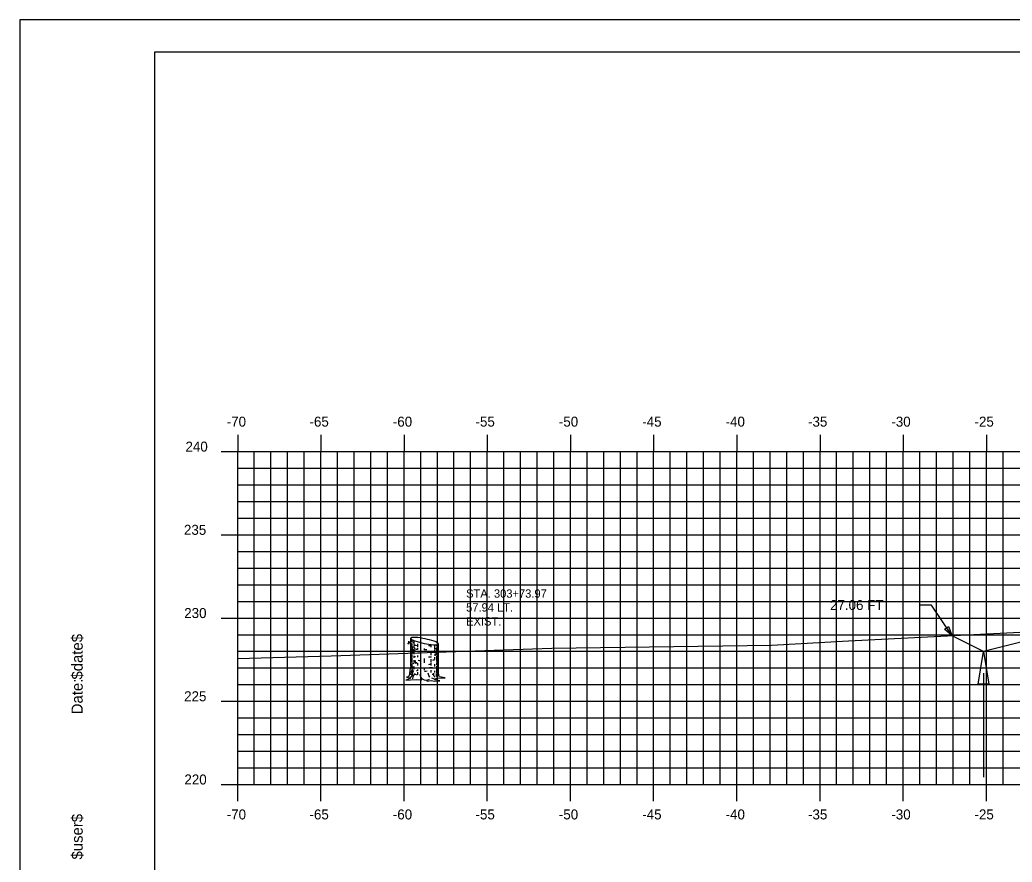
# Model space of a CAD drawing. Extents: x 1136767 to 1136937, y 608981 to 609091.
# Drawn here: x 1136767.3 to 1136826.9, y 609040.7 to 609091.3 of the extents above; entities that cross this region are included whole.
import ezdxf

# ---------------------------------------------------------------- set-up
doc = ezdxf.new("R2010")
doc.units = 0
for name, color, linetype in [('BORDER', 7, 'Continuous'), ('D_Drainage_Ditch_Line', 7, 'Continuous'), ('D_Roadway_SlopeLines', 7, 'Continuous'), ('D_Text_Monospaced', 7, 'Continuous'), ('D_Text_Standard', 7, 'Continuous'), ('H_V ANNOTATION', 7, 'Continuous'), ('MAJOR', 7, 'Continuous'), ('MINOR', 7, 'Continuous'), ('PLOT BOUNDARY', 7, 'Continuous'), ('S_Roadway_Centerline', 7, 'Continuous'), ('S_Trees_Conifer_Pay', 7, 'Continuous')]:
    doc.layers.add(name, color=color, linetype=linetype)

msp = doc.modelspace()

# ---------------------------------------------------------------- linework, layer by layer
at = {"layer": 'BORDER'}
msp.add_lwpolyline([(1136775.383, 608984.335), (1136935.383, 608984.335), (1136935.383, 609089.335), (1136775.383, 609089.335)], close=True, dxfattribs=at)
at = {"layer": 'D_Drainage_Ditch_Line'}
msp.add_line((1136825.208, 609052.015), (1136825.208, 609045.772), dxfattribs=at)
msp.add_lwpolyline([(1136825.536, 609051.359), (1136824.88, 609051.359), (1136825.208, 609053.328)], close=True, dxfattribs=at)
at = {"layer": 'D_Roadway_SlopeLines'}
msp.add_line((1136825.208, 609053.328), (1136823.319, 609054.272), dxfattribs=at)
msp.add_lwpolyline([(1136835.383, 609055.871), (1136831.383, 609054.871), (1136825.208, 609053.328)], dxfattribs=at)
at = {"layer": 'D_Text_Standard'}
msp.add_lwpolyline([(1136823.319, 609054.272), (1136822.078, 609056.116), (1136821.398, 609056.116)], dxfattribs=at)
msp.add_lwpolyline([(1136823.319, 609054.272), (1136822.874, 609054.674), (1136823.115, 609054.836)], close=True, dxfattribs=at)
at = {"layer": 'MAJOR'}
for p, q in [((1136780.383, 609066.337), (1136780.383, 609065.335)), ((1136785.383, 609066.337), (1136785.383, 609065.335)), ((1136790.383, 609066.337), (1136790.383, 609065.335)), ((1136795.383, 609066.337), (1136795.383, 609065.335)), ((1136800.383, 609066.337), (1136800.383, 609065.335)), ((1136805.383, 609066.337), (1136805.383, 609065.335)), ((1136810.383, 609066.337), (1136810.383, 609065.335)), ((1136815.383, 609066.337), (1136815.383, 609065.335)), ((1136820.383, 609066.337), (1136820.383, 609065.335)), ((1136825.383, 609066.337), (1136825.383, 609065.335)), ((1136779.381, 609065.335), (1136780.383, 609065.335)), ((1136780.383, 609065.335), (1136920.383, 609065.335)), ((1136780.383, 609045.335), (1136780.383, 609065.335)), ((1136780.383, 609045.335), (1136780.383, 609065.335)), ((1136780.383, 609065.335), (1136920.383, 609065.335)), ((1136785.383, 609045.335), (1136785.383, 609065.335)), ((1136790.383, 609045.335), (1136790.383, 609065.335)), ((1136795.383, 609045.335), (1136795.383, 609065.335)), ((1136800.383, 609045.335), (1136800.383, 609065.335)), ((1136805.383, 609045.335), (1136805.383, 609065.335)), ((1136810.383, 609045.335), (1136810.383, 609065.335)), ((1136815.383, 609045.335), (1136815.383, 609065.335)), ((1136820.383, 609045.335), (1136820.383, 609065.335)), ((1136825.383, 609045.335), (1136825.383, 609065.335)), ((1136779.381, 609060.335), (1136780.383, 609060.335)), ((1136780.383, 609060.335), (1136920.383, 609060.335)), ((1136779.381, 609055.335), (1136780.383, 609055.335)), ((1136780.383, 609055.335), (1136920.383, 609055.335)), ((1136779.381, 609050.335), (1136780.383, 609050.335)), ((1136780.383, 609050.335), (1136920.383, 609050.335)), ((1136779.381, 609045.335), (1136780.383, 609045.335)), ((1136780.383, 609045.335), (1136920.383, 609045.335)), ((1136780.383, 609045.335), (1136920.383, 609045.335)), ((1136780.383, 609044.333), (1136780.383, 609045.335)), ((1136785.383, 609044.333), (1136785.383, 609045.335)), ((1136790.383, 609044.333), (1136790.383, 609045.335)), ((1136795.383, 609044.333), (1136795.383, 609045.335)), ((1136800.383, 609044.333), (1136800.383, 609045.335)), ((1136805.383, 609044.333), (1136805.383, 609045.335)), ((1136810.383, 609044.333), (1136810.383, 609045.335)), ((1136815.383, 609044.333), (1136815.383, 609045.335)), ((1136820.383, 609044.333), (1136820.383, 609045.335)), ((1136825.383, 609044.333), (1136825.383, 609045.335))]:
    msp.add_line(p, q, dxfattribs=at)
at = {"layer": 'MINOR'}
for p, q in [((1136781.383, 609045.335), (1136781.383, 609065.335)), ((1136782.383, 609045.335), (1136782.383, 609065.335)), ((1136783.383, 609045.335), (1136783.383, 609065.335)), ((1136784.383, 609045.335), (1136784.383, 609065.335)), ((1136786.383, 609045.335), (1136786.383, 609065.335)), ((1136787.383, 609045.335), (1136787.383, 609065.335)), ((1136788.383, 609045.335), (1136788.383, 609065.335)), ((1136789.383, 609045.335), (1136789.383, 609065.335)), ((1136791.383, 609045.335), (1136791.383, 609065.335)), ((1136792.383, 609045.335), (1136792.383, 609065.335)), ((1136793.383, 609045.335), (1136793.383, 609065.335)), ((1136794.383, 609045.335), (1136794.383, 609065.335)), ((1136796.383, 609045.335), (1136796.383, 609065.335)), ((1136797.383, 609045.335), (1136797.383, 609065.335)), ((1136798.383, 609045.335), (1136798.383, 609065.335)), ((1136799.383, 609045.335), (1136799.383, 609065.335)), ((1136801.383, 609045.335), (1136801.383, 609065.335)), ((1136802.383, 609045.335), (1136802.383, 609065.335)), ((1136803.383, 609045.335), (1136803.383, 609065.335)), ((1136804.383, 609045.335), (1136804.383, 609065.335)), ((1136806.383, 609045.335), (1136806.383, 609065.335)), ((1136807.383, 609045.335), (1136807.383, 609065.335)), ((1136808.383, 609045.335), (1136808.383, 609065.335)), ((1136809.383, 609045.335), (1136809.383, 609065.335)), ((1136811.383, 609045.335), (1136811.383, 609065.335)), ((1136812.383, 609045.335), (1136812.383, 609065.335)), ((1136813.383, 609045.335), (1136813.383, 609065.335)), ((1136814.383, 609045.335), (1136814.383, 609065.335)), ((1136816.383, 609045.335), (1136816.383, 609065.335)), ((1136817.383, 609045.335), (1136817.383, 609065.335)), ((1136818.383, 609045.335), (1136818.383, 609065.335)), ((1136819.383, 609045.335), (1136819.383, 609065.335)), ((1136821.383, 609045.335), (1136821.383, 609065.335)), ((1136822.383, 609045.335), (1136822.383, 609065.335)), ((1136823.383, 609045.335), (1136823.383, 609065.335)), ((1136824.383, 609045.335), (1136824.383, 609065.335)), ((1136826.383, 609045.335), (1136826.383, 609065.335)), ((1136780.383, 609064.335), (1136920.383, 609064.335)), ((1136780.383, 609064.335), (1136781.385, 609064.335)), ((1136780.383, 609063.335), (1136920.383, 609063.335)), ((1136780.383, 609063.335), (1136781.385, 609063.335)), ((1136780.383, 609062.335), (1136920.383, 609062.335)), ((1136780.383, 609062.335), (1136781.385, 609062.335)), ((1136780.383, 609061.335), (1136920.383, 609061.335)), ((1136780.383, 609061.335), (1136781.385, 609061.335)), ((1136780.383, 609059.335), (1136920.383, 609059.335)), ((1136780.383, 609059.335), (1136781.385, 609059.335)), ((1136780.383, 609058.335), (1136920.383, 609058.335)), ((1136780.383, 609058.335), (1136781.385, 609058.335)), ((1136780.383, 609057.335), (1136920.383, 609057.335)), ((1136780.383, 609057.335), (1136781.385, 609057.335)), ((1136780.383, 609056.335), (1136920.383, 609056.335)), ((1136780.383, 609056.335), (1136781.385, 609056.335)), ((1136780.383, 609054.335), (1136920.383, 609054.335)), ((1136780.383, 609054.335), (1136781.385, 609054.335)), ((1136780.383, 609053.335), (1136920.383, 609053.335)), ((1136780.383, 609053.335), (1136781.385, 609053.335)), ((1136780.383, 609052.335), (1136920.383, 609052.335)), ((1136780.383, 609052.335), (1136781.385, 609052.335)), ((1136780.383, 609051.335), (1136920.383, 609051.335)), ((1136780.383, 609051.335), (1136781.385, 609051.335)), ((1136780.383, 609049.335), (1136920.383, 609049.335)), ((1136780.383, 609049.335), (1136781.385, 609049.335)), ((1136780.383, 609048.335), (1136920.383, 609048.335)), ((1136780.383, 609048.335), (1136781.385, 609048.335)), ((1136780.383, 609047.335), (1136920.383, 609047.335)), ((1136780.383, 609047.335), (1136781.385, 609047.335)), ((1136780.383, 609046.335), (1136920.383, 609046.335)), ((1136780.383, 609046.335), (1136781.385, 609046.335))]:
    msp.add_line(p, q, dxfattribs=at)
at = {"layer": 'PLOT BOUNDARY'}
msp.add_lwpolyline([(1136767.29, 608981.276), (1136937.29, 608981.276), (1136937.29, 609091.276), (1136767.29, 609091.276)], close=True, dxfattribs=at)
at = {"layer": 'S_Roadway_Centerline'}
msp.add_lwpolyline([(1136780.383, 609052.901), (1136785.998, 609053.058), (1136799.265, 609053.516), (1136812.47, 609053.71), (1136817.103, 609053.957), (1136831.751, 609054.699), (1136832.454, 609054.732), (1136832.628, 609054.777), (1136839.561, 609056.512), (1136842.668, 609056.609), (1136850.536, 609056.833), (1136853.824, 609056.876), (1136860.977, 609056.984), (1136868.81, 609054.669), (1136873.512, 609053.256), (1136876.457, 609053.35), (1136883.752, 609054.319), (1136889.143, 609054.263), (1136898.28, 609054.112), (1136907.414, 609054.01), (1136909.643, 609054.024), (1136910.933, 609054.007), (1136920.383, 609053.799)], dxfattribs=at)
at = {"layer": 'S_Trees_Conifer_Pay'}
for p, q in [((1136790.781, 609052.47), (1136790.781, 609054.117)), ((1136790.853, 609054.045), (1136790.853, 609053.882)), ((1136790.853, 609053.815), (1136790.853, 609053.687)), ((1136790.97, 609053.984), (1136790.97, 609053.761)), ((1136791.199, 609053.788), (1136791.199, 609053.589)), ((1136792.445, 609052.06), (1136792.445, 609053.782)), ((1136790.853, 609053.5), (1136790.853, 609053.164)), ((1136790.913, 609053.489), (1136790.965, 609053.43)), ((1136790.97, 609053.672), (1136790.97, 609053.625)), ((1136790.97, 609053.29), (1136790.97, 609053.158)), ((1136791.199, 609053.531), (1136791.199, 609053.442)), ((1136791.589, 609053.514), (1136791.589, 609053.419)), ((1136791.995, 609053.746), (1136791.995, 609053.578)), ((1136791.995, 609053.341), (1136791.995, 609053.104)), ((1136792.215, 609053.726), (1136792.215, 609053.493)), ((1136792.215, 609053.453), (1136792.215, 609053.379)), ((1136792.34, 609053.734), (1136792.34, 609053.636)), ((1136792.34, 609053.562), (1136792.34, 609053.358)), ((1136792.34, 609053.3), (1136792.34, 609053.1)), ((1136792.398, 609053.745), (1136792.398, 609053.274)), ((1136792.398, 609053.209), (1136792.398, 609052.901)), ((1136790.853, 609053.127), (1136790.853, 609052.964)), ((1136790.853, 609052.917), (1136790.853, 609052.701)), ((1136790.853, 609052.67), (1136790.853, 609052.596)), ((1136790.97, 609053.047), (1136790.97, 609052.938)), ((1136790.97, 609052.802), (1136790.97, 609052.66)), ((1136791.199, 609053.094), (1136791.199, 609052.989)), ((1136791.199, 609052.623), (1136791.199, 609052.476)), ((1136791.589, 609052.901), (1136791.589, 609052.827)), ((1136791.589, 609052.802), (1136791.589, 609052.653)), ((1136791.995, 609052.86), (1136791.995, 609052.707)), ((1136791.995, 609052.664), (1136791.995, 609052.491)), ((1136792.215, 609052.975), (1136792.215, 609052.837)), ((1136792.34, 609053.053), (1136792.34, 609052.717)), ((1136792.34, 609052.664), (1136792.34, 609052.528)), ((1136792.398, 609052.854), (1136792.398, 609052.361)), ((1136790.853, 609052.555), (1136790.853, 609052.382)), ((1136790.97, 609052.433), (1136790.97, 609052.26)), ((1136791.199, 609052.244), (1136791.199, 609052.155)), ((1136791.589, 609052.361), (1136791.589, 609052.209)), ((1136791.995, 609052.213), (1136791.995, 609052.06)), ((1136792.215, 609052.565), (1136792.215, 609052.423)), ((1136792.215, 609052.161), (1136792.215, 609052.067)), ((1136792.34, 609052.429), (1136792.34, 609052.05)), ((1136792.398, 609052.308), (1136792.398, 609052.06)), ((1136791.777, 609051.603), (1136791.903, 609051.667)), ((1136792.215, 609051.667), (1136792.052, 609051.731))]:
    msp.add_line(p, q, dxfattribs=at)
for points in [[(1136790.736, 609053.848), (1136790.66, 609053.856), (1136790.588, 609053.757)], [(1136790.965, 609053.615), (1136790.928, 609053.541), (1136790.881, 609053.598), (1136790.823, 609053.667), (1136790.73, 609053.86), (1136790.666, 609053.907), (1136790.635, 609053.914)], [(1136790.95, 609053.362), (1136790.913, 609053.489), (1136790.85, 609053.605), (1136790.819, 609053.672), (1136790.75, 609053.819)], [(1136790.998, 609053.578), (1136791.029, 609053.493), (1136791.033, 609053.426), (1136791.002, 609053.362)], [(1136792.266, 609053.088), (1136792.272, 609053.183), (1136792.229, 609053.16), (1136792.229, 609053.066)], [(1136791.127, 609052.689), (1136791.115, 609052.612), (1136791.068, 609052.623), (1136791.08, 609052.789)], [(1136790.781, 609052.47), (1136790.73, 609052.209), (1136790.714, 609051.935), (1136790.656, 609051.81), (1136790.52, 609051.779), (1136790.751, 609051.741), (1136790.751, 609051.741), (1136790.745, 609051.694), (1136790.497, 609051.6), (1136790.772, 609051.616), (1136791.127, 609051.636), (1136791.449, 609051.626), (1136791.442, 609051.709), (1136791.59, 609051.626), (1136791.777, 609051.603), (1136791.753, 609051.535), (1136792.021, 609051.579), (1136792.241, 609051.552), (1136792.534, 609051.569), (1136792.245, 609051.626), (1136792.215, 609051.667), (1136792.377, 609051.725), (1136792.614, 609051.735), (1136792.855, 609051.735), (1136792.513, 609051.793), (1136792.472, 609051.873), (1136792.445, 609052.06)], [(1136790.955, 609052.182), (1136790.881, 609052.077), (1136790.876, 609051.904), (1136790.751, 609051.741)], [(1136790.856, 609052.328), (1136790.85, 609052.182), (1136790.802, 609052.114), (1136790.792, 609051.915)], [(1136791.192, 609052.077), (1136791.181, 609051.951), (1136791.107, 609051.908)], [(1136791.93, 609051.779), (1136791.863, 609051.873), (1136791.836, 609052.013)], [(1136792.157, 609052.02), (1136792.157, 609051.888), (1136792.245, 609051.789)], [(1136792.319, 609051.993), (1136792.314, 609051.877), (1136792.367, 609051.789), (1136792.377, 609051.725)], [(1136792.398, 609052.013), (1136792.419, 609051.935), (1136792.439, 609051.84)], [(1136790.913, 609051.688), (1136790.928, 609051.826), (1136791.002, 609051.955)], [(1136791.442, 609051.709), (1136791.368, 609051.85), (1136791.358, 609051.951)]]:
    msp.add_lwpolyline(points, dxfattribs=at)
for centre, radius, start, end in [((1136790.804, 609054.118), 0.0226, 168.2806, 179.96855), ((1136790.808, 609054.118), 0.0264, 179.96855, 190.7806), ((1136790.815, 609053.991), 0.0334, 185.78494, 196.05154), ((1136790.815, 609053.837), 0.0334, 185.78494, 196.05154), ((1136790.804, 609054.118), 0.0226, 156.59265, 168.2806), ((1136790.813, 609054.119), 0.0314, 190.7806, 203.48418), ((1136790.825, 609053.994), 0.0441, 196.05154, 210), ((1136790.825, 609053.84), 0.0441, 196.05154, 210), ((1136790.807, 609054.116), 0.0264, 145.7806, 156.59265), ((1136790.832, 609054.127), 0.0527, 203.48418, 213.2806), ((1136790.812, 609054.113), 0.0314, 133.07702, 145.7806), ((1136790.841, 609054.003), 0.0624, 210, 228.74941), ((1136790.841, 609053.849), 0.0624, 210, 228.74941), ((1136790.856, 609054.143), 0.0817, 213.2806, 227.61132), ((1136790.826, 609054.098), 0.0527, 123.2806, 133.07702), ((1136790.842, 609054.073), 0.0817, 108.94987, 123.2806), ((1136790.913, 609054.086), 0.172, 228.74941, 240), ((1136790.913, 609053.931), 0.172, 228.74941, 240), ((1136790.97, 609054.268), 0.251, 227.61132, 235.7806), ((1136790.897, 609053.914), 0.251, 100.7806, 108.94987), ((1136791.112, 609054.276), 0.571, 240, 242.9763), ((1136791.28, 609054.723), 0.802, 235.7806, 251.94061), ((1136791, 609053.372), 0.802, 84.62059, 100.7806), ((1136791.112, 609054.431), 0.571, 247.58675, 255.56834), ((1136792.637, 609058.885), 5.179, 251.94061, 258.2806), ((1136790.59, 609049.015), 5.179, 78.2806, 84.62059), ((1136792.637, 609058.885), 5.179, 258.2806, 264.62059), ((1136790.59, 609049.015), 5.179, 71.94061, 78.2806), ((1136791.947, 609053.176), 0.802, 55.7806, 71.94061), ((1136792.256, 609053.632), 0.251, 47.61132, 55.7806), ((1136792.37, 609053.756), 0.0817, 33.2806, 47.61132), ((1136792.394, 609053.772), 0.0527, 23.48418, 33.2806), ((1136792.419, 609053.783), 0.0264, 325.7806, 336.59265), ((1136792.414, 609053.781), 0.0314, 10.7806, 23.48418), ((1136792.423, 609053.782), 0.0226, 336.59265, 348.2806), ((1136792.419, 609053.782), 0.0264, 359.96855, 10.7806), ((1136792.423, 609053.782), 0.0226, 348.2806, 359.96855), ((1136790.815, 609053.393), 0.0334, 185.78494, 196.05154), ((1136791.113, 609053.833), 0.571, 242.95715, 255.55072), ((1136791.112, 609054.276), 0.571, 255.63335, 261.8968), ((1136791.613, 609057.794), 4.124, 261.8968, 263.76196), ((1136791.615, 609057.561), 4.124, 262.94416, 264.21507), ((1136791.613, 609057.35), 4.124, 264.04957, 266.29476), ((1136791.615, 609057.561), 4.124, 269.64186, 270), ((1136791.615, 609057.561), 4.124, 270, 271.92488), ((1136791.613, 609057.794), 4.124, 273.26691, 275.3045), ((1136792.227, 609054.527), 0.802, 264.62059, 280.7806), ((1136792.115, 609054.044), 0.571, 282.01543, 293.14027), ((1136792.114, 609053.833), 0.571, 292.94134, 300), ((1136792.33, 609053.986), 0.251, 280.7806, 288.94988), ((1136792.115, 609054.044), 0.571, 299.66328, 300), ((1136792.315, 609053.699), 0.172, 300, 311.25059), ((1136792.385, 609053.826), 0.0817, 288.94988, 303.2806), ((1136792.387, 609053.616), 0.0624, 311.25059, 330), ((1136792.401, 609053.802), 0.0527, 303.2806, 313.07702), ((1136792.415, 609053.786), 0.0314, 313.07702, 325.7806), ((1136792.403, 609053.607), 0.0441, 330, 343.94846), ((1136792.413, 609053.604), 0.0334, 0, 16.05154), ((1136792.413, 609053.604), 0.0334, 343.94846, 360), ((1136790.816, 609053.157), 0.0334, 185.78494, 196.05154), ((1136790.816, 609052.947), 0.0334, 185.78494, 196.05154), ((1136790.826, 609053.16), 0.0441, 196.05154, 210), ((1136790.826, 609052.95), 0.0441, 196.05154, 210), ((1136790.842, 609053.169), 0.0624, 210, 228.74941), ((1136790.842, 609052.959), 0.0624, 210, 228.74941), ((1136790.915, 609053.252), 0.172, 228.74941, 240), ((1136790.915, 609053.042), 0.172, 228.74941, 240), ((1136791.114, 609053.597), 0.571, 240, 242.81041), ((1136791.114, 609053.387), 0.571, 240, 242.81041), ((1136791.114, 609053.15), 0.571, 242.81041, 254.60173), ((1136791.114, 609053.597), 0.571, 253.07038, 261.8968), ((1136791.615, 609057.114), 4.124, 261.8968, 262.38753), ((1136791.615, 609056.904), 4.124, 264.54309, 266.85066), ((1136791.615, 609056.904), 4.124, 269.64186, 270), ((1136791.615, 609057.114), 4.124, 273.33241, 275.91902), ((1136791.615, 609056.904), 4.124, 276.85262, 278.1032), ((1136792.115, 609053.387), 0.571, 278.1032, 280.72928), ((1136792.115, 609053.387), 0.571, 293.14027, 300), ((1136792.115, 609053.15), 0.571, 293.14027, 300), ((1136792.115, 609053.597), 0.571, 299.66328, 300), ((1136792.315, 609053.252), 0.172, 300, 311.25059), ((1136792.315, 609053.042), 0.172, 300, 311.25059), ((1136792.315, 609052.805), 0.172, 300, 311.25059), ((1136792.387, 609053.169), 0.0624, 311.25059, 330), ((1136792.387, 609052.959), 0.0624, 311.25059, 330), ((1136792.387, 609052.722), 0.0624, 311.25059, 330), ((1136792.403, 609053.16), 0.0441, 330, 343.94846), ((1136792.403, 609052.95), 0.0441, 330, 343.94846), ((1136792.403, 609052.713), 0.0441, 330, 343.94846), ((1136792.413, 609053.157), 0.0334, 0, 16.05154), ((1136792.413, 609053.157), 0.0334, 343.94846, 360), ((1136792.413, 609052.947), 0.0334, 0, 16.05154), ((1136792.413, 609052.947), 0.0334, 343.94846, 360), ((1136792.413, 609052.71), 0.0334, 0, 16.05154), ((1136792.413, 609052.71), 0.0334, 343.94846, 360), ((1136790.816, 609052.513), 0.0334, 185.78494, 196.05154), ((1136790.816, 609052.097), 0.0334, 185.78494, 196.05154), ((1136790.826, 609052.516), 0.0441, 196.05154, 210), ((1136790.826, 609052.1), 0.0441, 196.05154, 210), ((1136790.842, 609052.525), 0.0624, 210, 228.74941), ((1136790.842, 609052.109), 0.0624, 210, 228.74941), ((1136790.915, 609052.607), 0.172, 228.74941, 240), ((1136790.915, 609052.191), 0.172, 228.74941, 240), ((1136791.114, 609052.952), 0.571, 240, 250.70928), ((1136791.114, 609052.757), 0.571, 242.72792, 251.49327), ((1136791.615, 609056.274), 4.124, 263.21039, 264.21507), ((1136791.615, 609056.274), 4.124, 269.86721, 270), ((1136791.615, 609056.274), 4.124, 270, 272.18834), ((1136791.615, 609056.668), 4.124, 273.68066, 275.28397), ((1136791.615, 609056.47), 4.124, 274.16025, 276.50094), ((1136792.126, 609052.958), 0.571, 291.97323, 298.76314), ((1136792.115, 609052.757), 0.571, 293.14027, 300), ((1136792.115, 609052.536), 0.571, 295.46862, 300), ((1136792.315, 609052.412), 0.172, 300, 311.25059), ((1136792.315, 609052.191), 0.172, 300, 311.25059), ((1136792.387, 609052.329), 0.0624, 311.25059, 330), ((1136792.387, 609052.109), 0.0624, 311.25059, 330), ((1136792.403, 609052.32), 0.0441, 330, 343.94846), ((1136792.403, 609052.1), 0.0441, 330, 343.94846), ((1136792.413, 609052.513), 0.0334, 0, 16.05154), ((1136792.413, 609052.317), 0.0334, 0, 16.05154), ((1136792.413, 609052.317), 0.0334, 343.94846, 360), ((1136792.413, 609052.097), 0.0334, 0, 16.05154), ((1136792.413, 609052.097), 0.0334, 343.94846, 360), ((1136791.114, 609052.536), 0.571, 258.36297, 261.8968), ((1136791.615, 609056.054), 4.124, 261.8968, 262.63158), ((1136791.615, 609056.054), 4.124, 276.48798, 277.55621)]:
    msp.add_arc(centre, radius, start, end, dxfattribs=at)

# ---------------------------------------------------------------- texts
at = {"layer": 'BORDER'}
for s, p in [('$date$', (1136771.068, 609051.64)), ('Date:', (1136771.068, 609049.552)), ('$user$', (1136771.068, 609040.827))]:
    msp.add_text(s, height=0.6696, rotation=90, dxfattribs=at).set_placement(p)
at = {"layer": 'D_Text_Monospaced'}
for s, height, p in [('STA. 303+73.97', 0.49998, (1136794.112, 609056.558)), ('57.94 LT.', 0.5, (1136794.112, 609055.724)), ('EXIST. ', 0.5, (1136794.112, 609054.884))]:
    msp.add_text(s, height=height, dxfattribs=at).set_placement(p)
at = {"layer": 'D_Text_Standard'}
msp.add_text('27.06 FT', height=0.6, dxfattribs=at).set_placement((1136815.986, 609055.816))
at = {"layer": 'H_V ANNOTATION'}
for s, p in [('-70', (1136779.725, 609066.835)), ('-65', (1136784.701, 609066.835)), ('-60', (1136789.709, 609066.835)), ('-55', (1136794.679, 609066.835)), ('-50', (1136799.687, 609066.835)), ('-45', (1136804.701, 609066.835)), ('-40', (1136809.709, 609066.835)), ('-35', (1136814.663, 609066.835)), ('-30', (1136819.671, 609066.835)), ('-25', (1136824.669, 609066.835)), ('240', (1136777.245, 609065.335)), ('235', (1136777.154, 609060.335)), ('230', (1136777.17, 609055.335)), ('225', (1136777.165, 609050.335)), ('220', (1136777.181, 609045.335)), ('-70', (1136779.725, 609043.235)), ('-65', (1136784.701, 609043.235)), ('-60', (1136789.709, 609043.235)), ('-55', (1136794.679, 609043.235)), ('-50', (1136799.687, 609043.235)), ('-45', (1136804.701, 609043.235)), ('-40', (1136809.709, 609043.235)), ('-35', (1136814.663, 609043.235)), ('-30', (1136819.671, 609043.235)), ('-25', (1136824.669, 609043.235))]:
    msp.add_text(s, height=0.6, dxfattribs=at).set_placement(p)
at = {"layer": 'MAJOR'}
msp.add_text('-', height=0.006, dxfattribs=at).set_placement((1136780.379, 609045.335))

doc.saveas('drawing.dxf')
